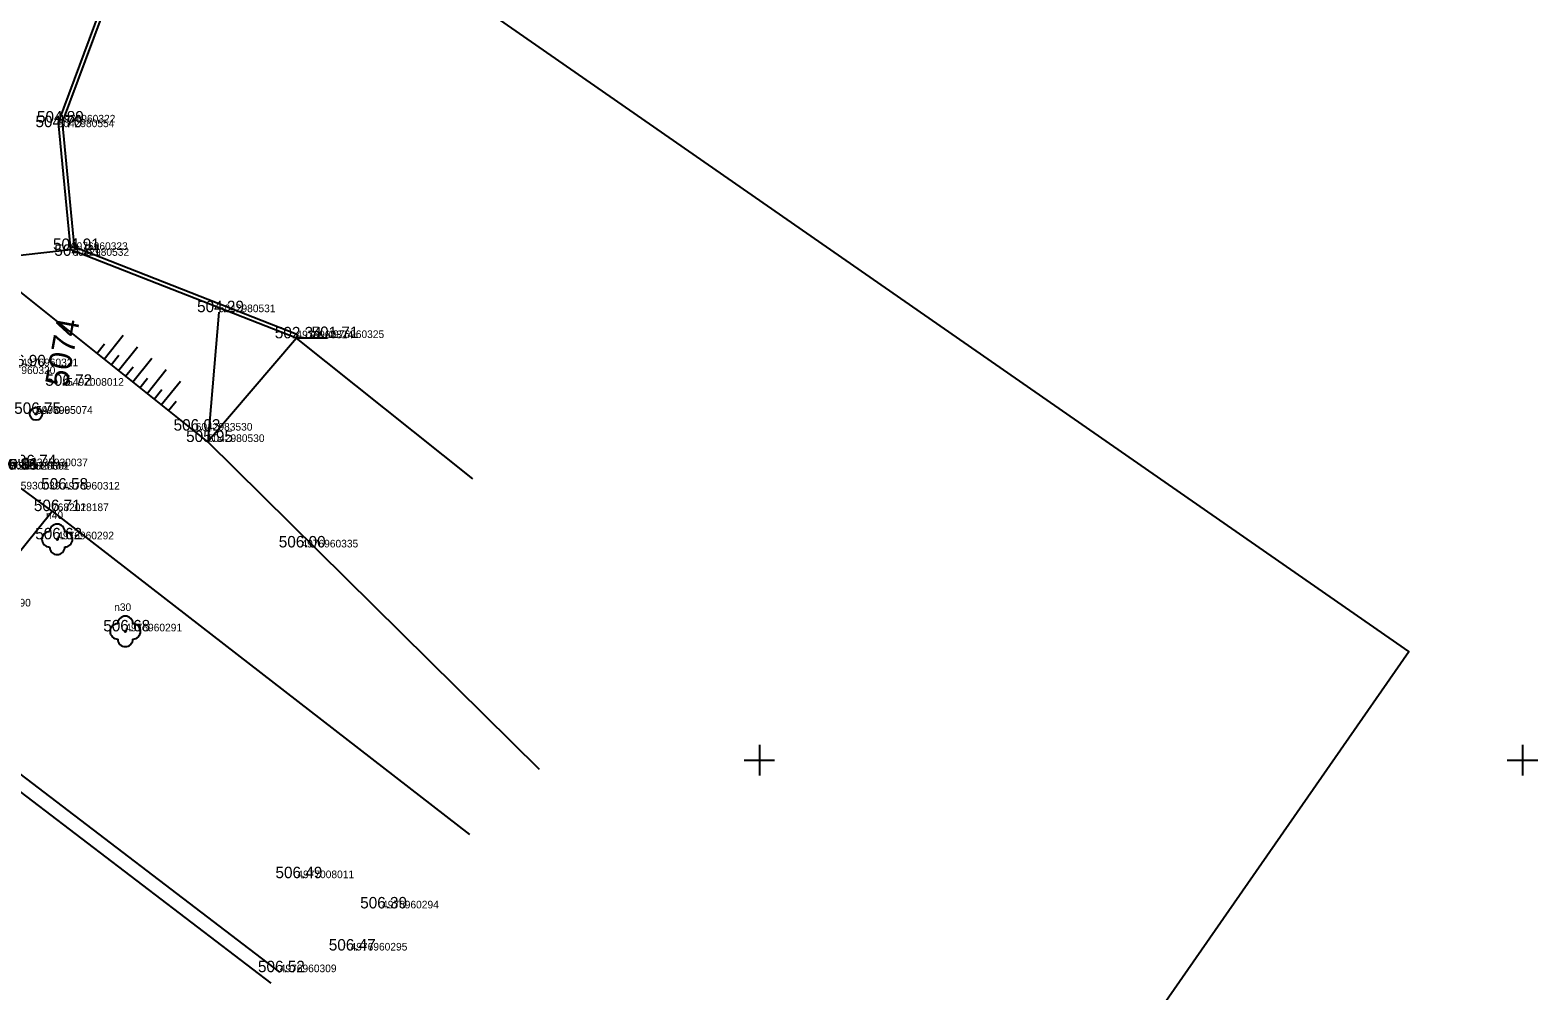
# Model space of a CAD drawing. Extents: x -669251 to -668549, y -1128351 to -1127698.
# Drawn here: x -668647.8 to -668549, y -1128015.1 to -1127952.2 of the extents above; entities that cross this region are included whole.
import ezdxf

# ---------------------------------------------------------------- set-up
doc = ezdxf.new("R2010")
doc.units = 0
for name, color, linetype in [('Vrstva 1', 7, 'Continuous'), ('Vrstva 10', 7, 'Continuous'), ('Vrstva 11', 7, 'Continuous'), ('Vrstva 14', 7, 'Continuous'), ('Vrstva 15', 7, 'Continuous'), ('Vrstva 2', 7, 'Continuous'), ('Vrstva 22', 7, 'Continuous'), ('Vrstva 3', 7, 'Continuous'), ('Vrstva 47', 7, 'Continuous'), ('Vrstva 5', 7, 'Continuous'), ('Vrstva 60', 7, 'Continuous'), ('Vrstva 61', 7, 'Continuous'), ('Vrstva 63', 7, 'Continuous'), ('Vrstva 7', 7, 'Continuous')]:
    doc.layers.add(name, color=color, linetype=linetype)

msp = doc.modelspace()

# ---------------------------------------------------------------- linework, layer by layer
at = {"layer": 'Vrstva 1'}
for p, q in [((-668645.975, -1127958.526), (-668645.975, -1127958.526)), ((-668645.91, -1127958.22), (-668645.91, -1127958.22)), ((-668645.1, -1127966.57), (-668645.1, -1127966.57)), ((-668645.011, -1127966.955), (-668645.011, -1127966.955)), ((-668635.418, -1127970.648), (-668635.418, -1127970.648)), ((-668630.33, -1127972.36), (-668630.33, -1127972.36)), ((-668628.3, -1127972.34), (-668628.3, -1127972.34)), ((-668645.352, -1127975.468), (-668645.352, -1127975.468)), ((-668647.39, -1127977.305), (-668647.39, -1127977.305)), ((-668647.39, -1127977.31), (-668647.39, -1127977.31)), ((-668647.39, -1127977.31), (-668647.39, -1127977.31)), ((-668636.927, -1127978.407), (-668636.927, -1127978.407)), ((-668636.138, -1127979.152), (-668636.138, -1127979.152)), ((-668647.71, -1127980.74), (-668647.71, -1127980.74)), ((-668645.62, -1127982.27), (-668645.62, -1127982.27)), ((-668646.34, -1127983.68), (-668646.34, -1127983.68)), ((-668646.34, -1127983.68), (-668646.34, -1127983.68)), ((-668646, -1127985.53), (-668646, -1127985.53)), ((-668630, -1127986.06), (-668630, -1127986.06)), ((-668641.54, -1127991.56), (-668641.54, -1127991.56)), ((-668630.27, -1128007.73), (-668630.27, -1128007.73)), ((-668624.72, -1128009.71), (-668624.72, -1128009.71)), ((-668626.78, -1128012.47), (-668626.78, -1128012.47)), ((-668631.42, -1128013.89), (-668631.42, -1128013.89))]:
    msp.add_line(p, q, dxfattribs=at)
at = {"layer": 'Vrstva 10'}
for p, q in [((-668645.91, -1127958.22), (-668642.688, -1127949.525)), ((-668645.661, -1127958.195), (-668642.453, -1127949.61)), ((-668645.1, -1127966.57), (-668645.91, -1127958.22)), ((-668644.866, -1127966.393), (-668645.661, -1127958.195)), ((-668630.33, -1127972.36), (-668645.1, -1127966.57)), ((-668630.238, -1127972.127), (-668644.866, -1127966.393)), ((-668630.33, -1127972.36), (-668630.238, -1127972.127))]:
    msp.add_line(p, q, dxfattribs=at)
at = {"layer": 'Vrstva 11'}
msp.add_line((-668631.42, -1128013.89), (-668653.17, -1127997.29), dxfattribs=at)
at = {"layer": 'Vrstva 14'}
for p, q in [((-668645.1, -1127966.57), (-668651.053, -1127967.224)), ((-668636.138, -1127979.152), (-668651.053, -1127967.224)), ((-668635.418, -1127970.648), (-668636.138, -1127979.152)), ((-668630.33, -1127972.36), (-668636.138, -1127979.152)), ((-668618.768, -1127981.569), (-668630.33, -1127972.36)), ((-668614.404, -1128000.61), (-668636.138, -1127979.152))]:
    msp.add_line(p, q, dxfattribs=at)
at = {"layer": 'Vrstva 15'}
for p, q in [((-668643.397, -1127973.347), (-668642.897, -1127972.722)), ((-668642.929, -1127973.721), (-668641.679, -1127972.159)), ((-668642.46, -1127974.096), (-668641.96, -1127973.471)), ((-668641.991, -1127974.471), (-668640.742, -1127972.909)), ((-668641.054, -1127975.22), (-668639.805, -1127973.658)), ((-668641.523, -1127974.846), (-668641.023, -1127974.221)), ((-668640.117, -1127975.97), (-668638.868, -1127974.408)), ((-668640.586, -1127975.595), (-668640.086, -1127974.97)), ((-668639.648, -1127976.345), (-668639.149, -1127975.72)), ((-668639.18, -1127976.719), (-668637.931, -1127975.157)), ((-668638.711, -1127977.094), (-668638.212, -1127976.469))]:
    msp.add_line(p, q, dxfattribs=at)
at = {"layer": 'Vrstva 22'}
for centre in [(-668646, -1127985.53), (-668641.54, -1127991.56)]:
    msp.add_circle(centre, 0.05, dxfattribs=at)
for centre, start, end in [((-668646, -1127985.03), 0, 180), ((-668646.5, -1127985.53), 90, 270), ((-668645.5, -1127985.53), 270, 90), ((-668646, -1127986.03), 180, 0), ((-668641.54, -1127991.06), 0, 180), ((-668642.04, -1127991.56), 90, 270), ((-668641.04, -1127991.56), 270, 90), ((-668641.54, -1127992.06), 180, 0)]:
    msp.add_arc(centre, 0.5, start, end, dxfattribs=at)
at = {"layer": 'Vrstva 5'}
msp.add_line((-668631.975, -1128014.617), (-668653.726, -1127998.018), dxfattribs=at)
at = {"layer": 'Vrstva 60'}
msp.add_lwpolyline([(-668788.581, -1128325.447), (-668557.456, -1127992.872), (-668787.384, -1127833.082), (-669018.509, -1128165.657)], close=True, dxfattribs=at)
at = {"layer": 'Vrstva 61'}
for p, q in [((-668600, -1127999), (-668600, -1128001)), ((-668550, -1127999), (-668550, -1128001)), ((-668601, -1128000), (-668599, -1128000)), ((-668551, -1128000), (-668549, -1128000))]:
    msp.add_line(p, q, dxfattribs=at)
at = {"layer": 'Vrstva 63'}
for radius in [0.412, 0.412, 0.05, 0.05]:
    msp.add_circle((-668647.39, -1127977.31), radius, dxfattribs=at)
at = {"layer": 'Vrstva 7'}
for p, q in [((-668628.3, -1127972.34), (-668630.33, -1127972.36)), ((-668646.34, -1127983.68), (-668652.73, -1127979.02)), ((-668655.35, -1127994.9), (-668646.34, -1127983.68)), ((-668646.34, -1127983.68), (-668618.98, -1128004.86))]:
    msp.add_line(p, q, dxfattribs=at)

# ---------------------------------------------------------------- texts
at = {"layer": 'Vrstva 2'}
for s, p in [('4976960322', (-668645.91, -1127958.22)), ('6042980554', (-668645.975, -1127958.526)), ('4976960323', (-668645.1, -1127966.57)), ('6042980532', (-668645.011, -1127966.955)), ('6042980531', (-668635.418, -1127970.648)), ('4976960324', (-668630.33, -1127972.36)), ('4976960325', (-668628.3, -1127972.34)), ('4976960321', (-668648.35, -1127974.19)), ('4976960320', (-668649.84, -1127974.7)), ('5497008012', (-668645.352, -1127975.468)), ('4976965074', (-668647.39, -1127977.31)), ('4977005074', (-668647.39, -1127977.31)), ('5496995074', (-668647.39, -1127977.305)), ('6042983530', (-668636.927, -1127978.407)), ('6042980530', (-668636.138, -1127979.152)), ('7682018189', (-668649.09, -1127980.94)), ('7682028189', (-668649.09, -1127980.94)), ('7960020601', (-668648.913, -1127980.97)), ('4335930037', (-668647.71, -1127980.74)), ('4335930039', (-668649.51, -1127982.26)), ('4976960312', (-668645.62, -1127982.27)), ('7682018187', (-668646.34, -1127983.68)), ('7682028187', (-668646.34, -1127983.68)), ('4976960292', (-668646, -1127985.53)), ('4976960335', (-668630, -1127986.06)), ('4976960290', (-668651.45, -1127989.93)), ('4976960291', (-668641.54, -1127991.56)), ('4977008011', (-668630.27, -1128007.73)), ('4976960294', (-668624.72, -1128009.71)), ('4976960295', (-668626.78, -1128012.47)), ('4976960309', (-668631.42, -1128013.89))]:
    msp.add_text(s, height=0.5, dxfattribs=at).set_placement(p)
at = {"layer": 'Vrstva 3'}
for s, p in [('504.70 ', (-668647.426, -1127958.526)), ('504.89 ', (-668647.328, -1127958.22)), ('504.91 ', (-668646.28, -1127966.57)), ('504.81 ', (-668646.189, -1127966.955)), ('504.29 ', (-668636.836, -1127970.648)), ('502.34 ', (-668631.745, -1127972.36)), ('501.71 ', (-668629.337, -1127972.34)), ('506.90 ', (-668649.816, -1127974.19)), ('506.72 ', (-668646.781, -1127975.468)), ('506.75 ', (-668648.819, -1127977.305)), ('506.75 ', (-668648.819, -1127977.31)), ('506.75 ', (-668648.819, -1127977.31)), ('506.03 ', (-668638.377, -1127978.407)), ('505.95 ', (-668637.555, -1127979.152)), ('506.86 ', (-668650.365, -1127980.97)), ('506.91 ', (-668650.284, -1127980.94)), ('506.91 ', (-668650.284, -1127980.94)), ('506.74 ', (-668649.139, -1127980.74)), ('506.58 ', (-668647.049, -1127982.27)), ('506.71 ', (-668647.532, -1127983.68)), ('506.71 ', (-668647.532, -1127983.68)), ('506.62 ', (-668647.442, -1127985.53)), ('506.00 ', (-668631.486, -1127986.06)), ('506.68 ', (-668642.982, -1127991.56)), ('506.49 ', (-668631.702, -1128007.73)), ('506.39 ', (-668626.152, -1128009.71)), ('506.47 ', (-668628.209, -1128012.47)), ('506.52 ', (-668632.849, -1128013.89))]:
    msp.add_text(s, height=0.75, dxfattribs=at).set_placement(p)
at = {"layer": 'Vrstva 47'}
for s, p in [('n40', (-668646.729, -1127984.194)), ('n30', (-668642.269, -1127990.224))]:
    msp.add_text(s, height=0.499, dxfattribs=at).set_placement(p)
at = {"layer": 'Vrstva 63'}
msp.add_text('5074', height=1.5, rotation=79.50139, dxfattribs=at).set_placement((-668645.339, -1127975.61))
msp.add_text('5074', height=1.5, rotation=79.50139, dxfattribs=at).set_placement((-668645.339, -1127975.61))

doc.saveas('drawing.dxf')
